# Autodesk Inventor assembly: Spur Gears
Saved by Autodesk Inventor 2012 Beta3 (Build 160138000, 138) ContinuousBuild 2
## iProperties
Created: 2010-12
Part Number: Spur Gears
Document SubType Name: Assembly
Designer: Thom Tremblay
Categories: <?xml version="1.0" encoding="UTF-16"?> <MemberInstance><Categories><FamilyTemplate/><ParamToTemplateMap><ParamToTemplate><ParamToTemplate CategoryParameter="//
ClientObjectVersion: 1
Author: Thom Tremblay
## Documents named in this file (2)
- C:\Inventor 2012 Essentials\Assemblies\Chapter 6\c6-01\Design Accelerator\Spur Gears2.iam
- C:\Inventor 2012 Essentials\Assemblies\Chapter 6\c6-01\Design Accelerator\Spur Gear22.ipt
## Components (1 placed, 1 different names)
1. Spur Gear2:1
